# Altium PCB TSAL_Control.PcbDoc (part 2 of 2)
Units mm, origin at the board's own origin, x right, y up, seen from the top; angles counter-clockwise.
Board outline 110 x 55.6 mm, 4 copper layers (Top Layer, GND, PWR, Bottom Layer), stack 1.488 mm thick; 121 components, 67 nets, 352 pads, 66 vias.
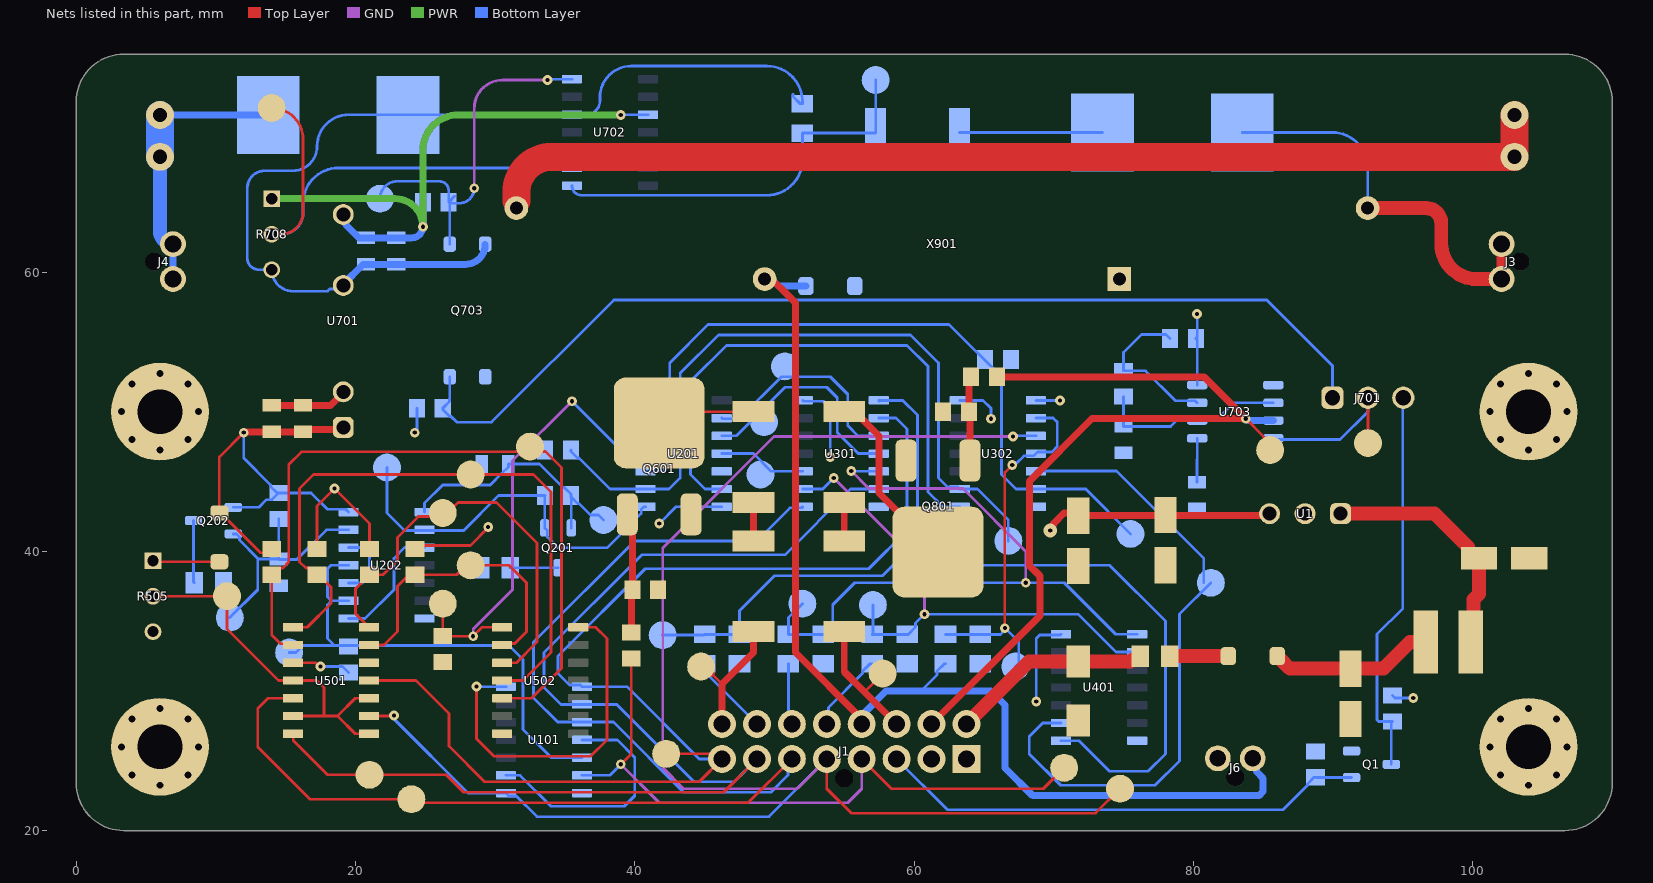
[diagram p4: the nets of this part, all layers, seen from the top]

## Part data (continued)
U301: library part CMP-00216-1, "XOR Gate, 4000/14000/40000 Series, 4-Func, 2-Input, CMOS, PDSO14", Case/Package=SOP, Load Capacitance (CL)=50pF, Max Operating Temperature=125°C, Max Supply Voltage=18V, Min Operating Temperature=-55°C, Min Supply Voltage=3V, Nominal Supply Voltage=5V, Package Body Material=Plastic, Package Equivalence Code=SOP14,.25, Package Shape=Rectangular, Package Style="SMALL OUTLINEMeter", Peak Reflow Temperature (Cel)=260°C, Power Supplies=5/15V, Temperature Grade=MILITARY
U401: library part CMP-00215-1, "NAND Gate, 4000/14000/40000 Series, 3-Func, 3-Input, CMOS, CDIP14", Case/Package=DIP, Max Operating Temperature=125°C, Max Supply Voltage=15V, Min Operating Temperature=-55°C, Min Supply Voltage=5V, Nominal Supply Voltage=10V, Package Body Material=Metal, Package Shape=Rectangular, Package Style=IN-LINEMeter, Temperature Grade=MILITARY
U501 U702: library part CMP-014-00006-1, "Comparator, 4 Func, 5000uV Offset-Max, 300ns Response Time, BIPolar, PDSO14", Case/Package=SOP, Max Operating Temperature=70°C, Min Operating Temperature=0°C, Nominal Supply Voltage=5V
U701: library part CMP-019-00001-1, "WPME-FISM Fixed Isolated SIP/SMT Module"
U703: library part CMP-00181-3, "Precision timer for -55 to 85C operation 8-SOIC -40 to 85", Case/Package=SOIC, Frequency=500kHz, High Level Output Current=-200mA, Low Level Output Current=200mA, Manufacturer="Texas Instruments", Manufacturer Part Number=SA555D, Max Operating Temperature=85°C, Max Supply Voltage=16V, Min Operating Temperature=-40°C, Min Supply Voltage=4.5V, Nominal Supply Current=2mA, Operating Supply Current=10mA, Package Quantity=75, Quiescent Current=15mA
X901: library part CMP-00224-2, "Dry Reed Relay, SPST-NC, 3500V switching voltage, 3A, 10kV isolation coil-contacts, 5504-24-1"

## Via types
v1: diameter 0.7, hole 0.5, Top Layer to Bottom Layer, tented both sides, 32 vias
v2: diameter 0.7, hole 0.3, Top Layer to Bottom Layer, tented both sides, 29 vias
v3: diameter 1.5, hole 1.5, Top Layer to Bottom Layer, tented both sides, 4 vias
v4: diameter 1, hole 0.3, Top Layer to Bottom Layer, tented both sides, 1 vias

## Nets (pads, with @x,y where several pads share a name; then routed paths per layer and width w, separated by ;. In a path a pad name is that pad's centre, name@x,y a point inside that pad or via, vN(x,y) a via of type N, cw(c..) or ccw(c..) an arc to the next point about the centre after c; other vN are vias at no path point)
+5TS: C701.1 C702.1 R706.1 R708.1 U701.4 U702.3 | length 43.9
  PWR w0.5: R708.1@14,65.25 22.825,65.25 cw(c22.825,63.25) v2(24.825,63.25) 24.825,68.71 cw(c27.365,68.71) 27.365,71.25 v2(39,71.25)
  Bottom Layer w0.2: v2(39,71.25) 39.02,71.27 U702.3@40.95,71.27
  Bottom Layer w0.5: U701.4@19.125,64.12 19.316,63.929 19.316,63.384 20.25,62.45 C701.1@22.921,62.45 ; C701.1@22.921,62.45 24.025,62.45 ccw(c24.025,63.25) v2(24.825,63.25) R706.1@24.825,65
+12: C3.1 C4.1 C703.1 C704.1 D501.K J1.7 Q202.G R1.1 R111.2 R202.1 R501.1 R502.1 R503.1 R504.1 R702.1 R704.1 U1.3 U101.14 U201.14 U202.14 U301.14 U302.1 U302.14 U401.14 U501.3 U502.14 U701.1 U703.8 | length 126.5
  Top Layer w0.2: v2(12,48.5) 10.25,46.75 D501.K@10.25,42.75 10.35,42.75 13.2,39.9 13.725,39.9 R502.1@14,40.175 ; U501.3@15.525,32.02 17.133,32.02 v2@17.403,31.75 ; R501.1@17.25,40.175 17.25,43.25 v2(18.5,44.5) 21,42 R503.1@21,40.175 ; R504.1@24.5,40.175 24.75,40.425 28.234,40.425 29.5,41.691 v2(29.5,41.75) ; v2(28.669,30.328) 28.669,26.581 29.919,25.331 36.831,25.331 38,26.5 38,33.75 37.19,34.56 U502.14@35.95,34.56
  Top Layer w0.5: v2(12,48.5) 12.054,48.5 12.104,48.55 C703.1@14,48.55 C704.1@16.25,48.55 16.415,48.715 18.96,48.715 U701.1@19.125,48.88 ; v4(69.75,41.5) 69.75,41.635 70,41.885 70,42 70.75,42.75 71.55,42.75 C3.1@71.75,42.55 85.31,42.55 U1.3@85.46,42.7
  Bottom Layer w0.2: Q202.G@11.25,43.15 13.069,43.15 13.619,43.7 14.025,43.7 R202.1@14.5,44.175 ; v2(12,48.5) 12,46.675 13.925,44.75 13.925,44.65 14.4,44.175 R202.1@14.5,44.175 ; v2(17.5,31.75) 19.075,31.75 R111.2@19.5,31.325 ; U202.14@19.5,42.81 19.3,43.01 17.99,43.01 16.825,44.175 R202.1@14.5,44.175 ; v2(24.25,48.5) 24.4,48.65 R702.1@24.4,50.25 ; v2(28.669,30.328) 28.672,30.328 28.75,30.25 28.81,30.31 U101.14@30.775,30.31 ; v2@41.768,42 42.958,43.19 U201.14@46.225,43.19 ; U301.14@52.025,50.81 52.085,50.75 53.5,50.75 54,50.25 v2(54,46.75) ; U302.14@63.275,50.81 64.94,50.81 65.5,50.25 v2(65.5,49.5) ; U302.1@68.725,50.81 v2(70.44,50.81) ; v2(68.75,29.25) 68.75,33.75 69,34 70.465,34 U401.14@70.525,34.06 ; v2(80.25,57) 80.275,56.975 80.275,55.35 R704.1@80.175,55.25 80.275,55.15 U703.8@80.275,51.905 ; R1.1@94.25,29.675 94.425,29.5 v2(95.75,29.5)
  other v2: 41.75,42
AIR+_Coil: AIR+_COIL.1 R3.2 R4.1 U301.1 U401.8 | length 73.9
  Bottom Layer w0.2: AIR+_COIL.1@42,34 44.95,34 R3.2@45,34.05 R4.1@47.5,34.05 47.5,35.75 50,38.25 57.75,38.25 58.5,39 ; U301.1@57.535,50.75 U301.1@57.475,50.81 59.19,50.81 60.25,49.75 60.25,40.75 58.5,39 ; U401.8@70.525,26.44 71.81,26.44 74,24.25 76.75,24.25 78,25.5 78,35 74,39 58.5,39
AIR+_Coil_30V: J1.10 R3.1 | length 5.9
  Bottom Layer w0.2: R3.1@45,31.95 45.238,31.712 45.238,31.142 J1.10@48.75,27.631
AIR+_Implausibility: AIR+_IMPL.1 U201.9 U301.3 | length 15.6
  Bottom Layer w0.2: U201.9@46.225,49.54 46.265,49.5 47.5,49.5 50.5,52.5 54,52.5 55.25,51.25 55.25,49 55.98,48.27 U301.3@57.475,48.27
AIR+_SCS: AIR+_SCS.1 R502.2 U501.2 U502.5 | length 55
  Top Layer w0.2: U501.2@15.525,33.29 15.432,33.383 14.617,33.383 14,34 R502.2@14,38.325 14.475,38.8 14.8,38.8 15.225,39.225 15.225,46.225 16.125,47.125 31.483,47.125 31.513,47.156 32.094,47.156 32.125,47.125 AIR+_SCS.1@32.5,47.5 32.844,47.156 33.594,47.156 34.75,46 34.75,31.628 32.602,29.48 U502.5@30.5,29.48
AIR+_State: AIR+_STATE.1 J1.1 U101.1 U301.2 U501.11 | length 88.3
  Top Layer w0.2: U501.11@20.975,30.75 24.338,30.75 26.7,28.388 26.7,26.05 29.25,23.5 44.619,23.5 J1.1@46.25,25.131 45.763,25.131 45.393,25.5 AIR+_STATE.1@42.25,25.5
  Bottom Layer w0.2: J1.1@46.25,25.131 44.619,25.131 39.44,30.31 U101.1@36.225,30.31 36.108,30.427 35.323,30.427 34.5,31.25 34.5,32.5 40.75,38.75 56.75,38.75 59.5,41.5 59.5,48.75 58.71,49.54 U301.2@57.475,49.54
AIR-_Coil: AIR-_COIL.1 R5.2 R6.1 U301.5 U401.1 | length 50.7
  GND w0.2: v2@55.51,45.74 56.75,44.5 63.5,44.5 68,40 v2(68,37.75)
  Bottom Layer w0.2: AIR-_COIL.1@52,36.25 51,35.25 R5.2@51,34.05 53.5,34.05 53.65,34.05 54.175,34.575 54.175,36.175 55.75,37.75 70.75,37.75 74.44,34.06 U401.1@75.975,34.06 ; v2(55.5,45.75) 55.52,45.73 U301.5@57.475,45.73
AIR-_Coil_30V: J1.11 R5.1 | length 4.4
  Bottom Layer w0.2: R5.1@51,31.95 51,27.881 J1.11@51.25,27.631
AIR-_Implausibility: AIR-_IMPL.1 U201.10 U301.4 | length 16.1
  Bottom Layer w0.2: U201.10@46.225,48.27 47.27,48.27 50.75,51.75 53.75,51.75 54.5,51 54.5,48.5 56,47 U301.4@57.475,47
AIR-_SCS: AIR-_SCS.1 R503.2 U501.14 U502.3 | length 31.3
  Top Layer w0.2: U501.14@20.975,34.56 20,35.535 20,37.325 R503.2@21,38.325 21.975,38.325 23,39.35 23,41 24.5,42.5 26.164,42.5 AIR-_SCS.1@26.414,42.75 ; AIR-_SCS.1@26.25,42.75 AIR-_SCS.1@26.414,42.75 ; U502.3@30.5,32.02 31.52,32.02 33,33.5 33,40.599 30.099,43.5 27.338,43.5 26.588,42.75 AIR-_SCS.1@26.414,42.75
AIR-_State: AIR-_STATE.1 J1.2 U101.2 U301.6 U501.7 | length 86.3
  Top Layer w0.2: U501.7@15.525,26.94 15.543,26.922 15.543,26.457 18,24 AIR-_STATE.1@21,24 26.5,24 27.75,22.75 46.369,22.75 J1.2@48.75,25.131
  Bottom Layer w0.2: J1.2@48.75,25.131 47.119,23.5 44.25,23.5 38.71,29.04 U101.2@36.225,29.04 34.71,29.04 33.5,30.25 33.5,32.75 40.5,39.75 50.75,39.75 55.46,44.46 U301.6@57.475,44.46
Discharge_Resistor: J2.1 J2.2 X901.1 | length 76.6
  Top Layer w2: X901.1@31.52,65.08 31.52,65.71 cw(c34.06,65.71) 34.06,68.25 J2.1@103,68.25 J2.2@103,71.25
GND: C1.2 C2.2 C3.2 C4.2 C201.2 C202.2 C703.2 C704.2 C705.2 C706.2 D1.2 D901.A J1.8 J6.1 MH1.1 MH2.1 MH3.1 MH4.1 Q1.S Q601.S Q703.3 Q801.S R2.2 R4.2 R6.2 R8.2 R10.2 R203.2 R204.2 R333.1 R444.1 R505.2 R555.1 R602.2 R802.2 U1.2 U101.7 U201.5 U201.7 U201.12 U202.7 U301.7 U302.7 U401.7 U501.12 U502.7 U701.2 U703.1 X901.3 | length 11.1
  Top Layer w0.2: v1(3.25,26) MH1.1@6,26
  Top Layer w0.5: C703.2@14,50.45 C704.2@16.25,50.45 18.207,50.45 19.125,51.368 U701.2@19.125,51.42 ; MH3.1@104,50 v1(104,52.75)
  other v1: 6,23.25 104,23.25 4,24 8,24 102,24 106,24 8.75,26 101.25,26 106.75,26 4,28 8,28 102,28 106,28 6,28.75 104,28.75 6,47.25 104,47.25 4,48 8,48 102,48 106,48 3.25,50 8.75,50 101.25,50 106.75,50 4,52 8,52 102,52 106,52 6,52.75
HV_Accu_SCS: HV_ACCU_SCS.1 R501.2 U501.1 U502.4 | length 47.6
  Top Layer w0.2: U501.1@15.525,34.56 16.55,34.56 18.25,36.26 18.25,37.425 17.35,38.325 R501.2@17.25,38.325 16.775,38.8 16.45,38.8 16,39.25 16,44.5 17,45.5 32.75,45.5 34,44.25 34,32.75 32,30.75 U502.4@30.5,30.75
HV_Accumulator: HV_ACCU.1 J1.4 U101.8 U302.3 U501.9 | length 121.3
  Top Layer w0.2: U501.9@20.975,28.21 22.71,28.21 v2(22.75,28.25) ; J1.4@53.75,25.131 53.75,23 55.5,21.25 73,21.25 HV_ACCU.1@74.75,23
  GND w0.2: J1.4@53.75,25.131 51.619,23 43.5,23 42,24.5 42,40.25 49.981,48.231 v2(67.081,48.231)
  Bottom Layer w0.2: v2(22.75,28.25) 22.846,28.154 22.846,27.904 28.06,22.69 U101.8@30.775,22.69 30.975,22.49 31.51,22.49 33,21 49.619,21 J1.4@53.75,25.131 ; v2(67.081,48.231) 67.231,48.231 67.27,48.27 U302.3@68.725,48.27
HV_Detection_DCBus: J701.1 Q703.4 R702.2 | length 74.5
  Bottom Layer w0.2: Q703.4@26.75,52.5 26.75,50.942 26.725,50.917 26.725,50.725 R702.2@26.25,50.25 26.25,50.15 26.725,49.675 26.825,49.675 27.25,49.25 29.75,49.25 38.5,58 85.25,58 89.96,53.29 J701.1@89.96,51
HV_Detection_Trigger: HV_DET_TRIG.1 J701.2 U703.4 | length 11.9
  Top Layer w0.2: HV_DET_TRIG.1@92.5,47.75 J701.2@92.5,51
  Bottom Layer w0.2: U703.4@85.725,48.095 85.82,48 90.5,48 92.5,50 J701.2@92.5,51
Implausibilities: C201.1 IMPLAUSIBILITIES.1 Q201.S R201.2 U202.1 | length 18.7
  Bottom Layer w0.2: U202.1@24.95,42.81 24.95,43.45 26.25,44.75 29.65,44.75 30.467,45.567 30.95,46.05 C201.1@30.95,46.25 33.175,46.25 34.85,44.575 34.95,44.575 35.425,44.1 R201.2@35.425,44 35.425,43.9 R201.2@35.45,43.875 ; Q201.S@35.45,41.675 R201.2@35.45,43.875 ; IMPLAUSIBILITIES.1@37.75,42.25 37.406,42.594 36.831,42.594 36,43.425 35.9,43.425 R201.2@35.45,43.875
Implausibilities_Undelayed: IMPL_UNDLY.1 Q201.G R201.1 U201.1 U202.2 | length 27.9
  Bottom Layer w0.2: IMPL_UNDLY.1@22.25,46 22.25,42.75 23.5,41.5 27.75,41.5 30.25,44 R201.1@33.575,44 33.55,43.975 Q201.G@33.55,41.675 33.736,41.489 33.736,41.014 34.5,40.25 38,40.25 40.457,42.707 40.457,42.99 40.657,43.19 U201.1@40.775,43.19
INV_HV_Detection: J701.3 Q1.D R1.2 | length 28.1
  Bottom Layer w0.2: Q1.D@94.175,24.75 94.175,27.75 R1.2@94.25,27.825 93.275,27.825 93.158,27.942 93.158,34.069 95,35.912 95,50.96 J701.3@95.04,51
INV_HV_Detection5V: J1.6 Q1.G R2.1 | length 35.1
  Bottom Layer w0.2: J1.6@58.75,25.131 62.381,21.5 86.425,21.5 88.175,23.25 88.175,23.35 88.65,23.825 R2.1@88.75,23.825 88.775,23.8 Q1.G@91.325,23.8
Latch_Reset: C202.1 LATCH_RST.1 Q202.S R202.2 U202.13 | length 18
  Bottom Layer w0.2: LATCH_RST.1@11,35.25 13,37.25 13,39.5 ; Q202.S@11.25,41.25 11.469,41.25 11.69,41.03 11.69,40.81 13,39.5 ; R202.2@14.5,42.325 C202.1@14.5,39.45 ; U202.13@19.5,41.54 17.923,41.54 15.79,39.407 14.543,39.407 C202.1@14.5,39.45 ; 13,39.5 13.05,39.45 C202.1@14.5,39.45
LV+_in: D1.1 F1.1 J1.16 | length 14.6
  Top Layer w1: J1.16@63.75,27.631 68.22,32.1 D1.1@71.75,32.1 75.489,32.1 75.614,32.225 76.075,32.225 76.2,32.35 F1.1@76.2,32.5
NetC1_1: C1.1 D2.K L1.1 | length 11.8
  Top Layer w1: D2.K@86,32.5 86,32.4 86.05,32.35 86.15,32.35 86.9,31.6 C1.1@91.25,31.6 93.6,31.6 95.5,33.5 L1.1@96.625,33.5
NetC2_1: C2.1 L1.2 U1.1 | length 17.8
  Top Layer w1: U1.1@90.54,42.7 97.25,42.7 99.65,40.3 99.65,39.8 99.95,39.5 C2.1@100.45,39.5 100.45,36.95 100.061,36.561 100.061,33.686 L1.2@99.875,33.5
NetC705_1: C705.1 U703.5 | length 3.2
  Bottom Layer w0.2: C705.1@80.25,44.95 80.25,46.587 80.275,46.612 U703.5@80.275,48.095
NetC706_1: C706.1 R705.2 U703.2 U703.6 | length 13.5
  Bottom Layer w0.2: R705.2@75,51.075 C706.1@75,48.95 78.374,48.95 78.789,49.365 U703.6@80.275,49.365 81.615,49.365 82.885,50.635 U703.2@85.725,50.635
NetD2_A: D2.A F1.2 | length 4.2
  Top Layer w1: F1.2@78.3,32.5 D2.A@82.5,32.5
NetD501_A: D501.A R505.1 | length 4.8
  Top Layer w0.2: R505.1@5.5,39.33 5.58,39.25 D501.A@10.25,39.25
NetQ201_D: Q201.D R203.1 | length 3.5
  Bottom Layer w0.2: R203.1@31.071,38.829 R203.1@31.141,38.829 ; R203.1@31.141,38.9 31.216,38.825 Q201.D@34.5,38.825
NetQ202_D: Q202.D R204.1 | length 4.5
  Bottom Layer w0.2: Q202.D@8.4,42.2 8.4,37.8 R204.1@8.45,37.75
NetQ601_D: Q601.D R604.2 | length 7.1
  Top Layer w0.2: Q601.D@41.75,49.2 42.55,50 R604.2@48.5,50
NetQ601_G: Q601.G R601.2 R602.1 | length 8.7
  Top Layer w0.5: Q601.G@39.464,42.65 39.825,42.289 R602.1@39.825,37.25 39.75,37.175 R601.2@39.75,34.175
NetQ801_D: Q801.D R804.2 | length 13.3
  Top Layer w0.5: R804.2@55,50 55.75,50 57.5,48.25 57.5,44.164 Q801.D@61.714,39.95
NetQ801_G: Q801.G R801.2 R802.1 | length 6.1
  Top Layer w0.5: Q801.G@64,46.5 64,49.925 R802.1@63.925,50 63.925,52.35 R801.2@64.075,52.5
NetR603_2: R603.2 R604.1 | length 2.7
  Top Layer w0.5: R603.2@48.5,40.75 R604.1@48.5,43.5
NetR704_2: R704.2 R705.1 U703.7 | length 11.5
  Bottom Layer w0.2: R704.2@78.325,55.25 78.05,55.525 76.275,55.525 75,54.25 R705.1@75,52.925 76.575,52.925 78.714,50.786 80.124,50.786 U703.7@80.275,50.635
NetR803_2: R803.2 R804.1 | length 2.7
  Top Layer w0.5: R803.2@55,40.75 R804.1@55,43.5
NetU101_4: U101.4 U101.9 | length 17.5
  Bottom Layer w0.2: U101.9@30.775,23.96 31.79,23.96 34,21.75 39.25,21.75 40,22.5 40,25.25 38.75,26.5 U101.4@36.225,26.5
No_Voltage_Relays_Closed: NO_HV_REL_CLS.1 R444.2 U201.3 U302.6 | length 53.6
  Bottom Layer w0.2: U201.3@40.775,45.73 41.98,45.73 42.5,46.25 42.5,53.5 45.25,56.25 62.5,56.25 66.25,52.5 66.25,45.5 67.29,44.46 U302.6@68.725,44.46 72.29,44.46 NO_HV_REL_CLS.1@75.5,41.25
Not_Intentional_Relay_State: NOT_INT_REL_STATE.1 U302.5 U401.9 | length 46.4
  Bottom Layer w0.2: U302.5@68.725,45.73 68.745,45.75 74.5,45.75 80.75,39.5 NOT_INT_REL_STATE.1@80.75,37.75 ; U401.9@70.525,27.71 69.21,27.71 68.25,26.75 68.25,25.5 70.5,23.25 77.25,23.25 79,25 79,35.5 NOT_INT_REL_STATE.1@81.25,37.75
Not_Safe_State: U202.10 U202.12 | length 4.9
  Bottom Layer w0.2: U202.10@19.5,37.73 20.48,37.73 21,38.25 21,39.75 20.48,40.27 U202.12@19.5,40.27
Out_HV_Comparator: Out_HV_Comparator.1 Q703.1 R706.2 U702.14 | length 27
  GND w0.2: v2@28.5,65.785 v2(28.5,66) 28.5,71.71 cw(c30.54,71.71) 30.54,73.75 v2(33.75,73.75)
  Bottom Layer w0.2: Out_HV_Comparator.1@21.75,65.25 cw(c23,65.25) 23,66.5 26,66.5 cw(c26,65.825) 26.675,65.825 R706.2@26.675,65 ; Q703.1@26.75,62 R706.2@26.75,64.925 ; R706.2@27.108,65.433 R706.2@26.675,65 ; v2(28.5,66) cw(c27.425,66) 27.425,64.925 R706.2@26.75,64.925 ; v2(33.75,73.75) 33.81,73.81 U702.14@35.5,73.81 ; R706.2@26.675,65 cw(c26.675,64.925) R706.2@26.75,64.925
Precharge_Coil: PRE_COIL.1 R7.2 R8.1 U301.9 U401.2 | length 38
  GND w0.2: v2(54.25,45.25) 60.75,38.75 v2(60.75,35.5)
  Bottom Layer w0.2: U301.9@52.025,44.46 53.46,44.46 v2(54.25,45.25) ; PRE_COIL.1@57.05,36.158 57.05,34.1 R7.2@57,34.05 59.583,34.05 60.107,34.575 60.107,34.857 v2(60.75,35.5) 71.75,35.5 74.46,32.79 U401.2@75.975,32.79
Precharge_Coil_30V: J1.12 R7.1 | length 5.8
  Bottom Layer w0.2: J1.12@53.75,27.631 53.863,27.744 53.863,28.813 56.325,31.275 56.325,31.425 56.85,31.95 R7.1@57,31.95
Precharge_Implausibility: PRE_IMPL.1 U201.11 U301.10 | length 6.3
  Bottom Layer w0.2: U201.11@46.225,47 48.5,47 49.77,45.73 U301.10@52.025,45.73
Precharge_SCS: PRE_SCS.1 R504.2 U501.13 U502.2 | length 23.3
  Top Layer w0.2: U501.13@20.975,33.29 22.04,33.29 23,34.25 23,37.5 23.642,38.142 24.317,38.142 24.5,38.325 27.252,38.325 27.502,38.575 27.825,38.575 PRE_SCS.1@28.25,39 ; PRE_SCS.1@27.584,38.821 PRE_SCS.1@27.584,38.834 ; PRE_SCS.1@27.825,38.594 PRE_SCS.1@27.584,38.834 ; PRE_SCS.1@28.575,39.325 PRE_SCS.1@28.25,39 ; U502.2@30.5,33.29 30.612,33.402 31.407,33.402 32.25,34.245 32.25,37.75 31,39 PRE_SCS.1@28.25,39 ; PRE_SCS.1@27.584,38.834 27.75,39 PRE_SCS.1@28.25,39
Precharge_State: J1.3 PRE_STATE.1 U101.3 U301.8 U501.5 | length 96.9
  Top Layer w0.2: U501.5@15.525,29.48 13.73,29.48 13,28.75 13,26 16.75,22.25 PRE_STATE.1@24,22.25 24.25,22 48.119,22 J1.3@51.25,25.131
  Bottom Layer w0.2: J1.3@51.25,25.131 50.971,24.852 50.971,23.971 49.75,22.75 43.5,22.75 38.48,27.77 U101.3@36.225,27.77 34.48,27.77 32.75,29.5 32.75,33.5 40,40.75 48.75,40.75 51.117,43.117 51.952,43.117 U301.8@52.025,43.19
Relays_Implausibility: R333.2 RELAYS_IMPL.1 U201.2 U302.9 | length 53.3
  Bottom Layer w0.2: R333.2@35.425,47.25 35.425,47.15 35.9,46.675 36,46.675 38.215,44.46 U201.2@40.775,44.46 42.46,44.46 43.25,45.25 43.25,52.75 46,55.5 59.75,55.5 61.75,53.5 61.75,45.25 62.398,44.602 63.133,44.602 U302.9@63.275,44.46 64.54,44.46 66.75,42.25 RELAYS_IMPL.1@66.75,40.75
Relays_State_Detection: RELAY_STATE_DET.1 U201.13 U302.8 | length 42.2
  Bottom Layer w0.2: U201.13@46.225,44.46 45.04,44.46 44,45.5 44,52.183 46.567,54.75 59.5,54.75 61,53.25 61,44.25 62.06,43.19 U302.8@63.275,43.19 63.25,43.165 RELAY_STATE_DET.1@63.25,40.75
Safe_State: R111.1 SAFE_STATE.1 U101.5 U202.9 U202.11 | length 36.2
  Bottom Layer w0.2: SAFE_STATE.1@15.25,32.75 15.737,32.75 16.237,33.25 18.5,33.25 ; U202.9@19.5,36.46 18.29,36.46 ; U202.11@19.5,39 18.25,39 18,38.75 18,36.75 18.29,36.46 ; U101.5@36.225,25.23 34.02,25.23 32,27.25 32,32.25 31,33.25 19.5,33.25 18.5,33.25 ; 18.29,36.46 18,36.17 18,33.75 18.5,33.25
Safe_State_Unlatched: U202.3 U202.8 | length 8.9
  Bottom Layer w0.2: U202.8@19.5,35.19 20.69,35.19 22.75,37.25 22.75,39.5 23.52,40.27 U202.3@24.95,40.27
SC_End: R9.2 R10.1 SC_END.1 U302.2 U302.4 | length 26.9
  Top Layer w0.2: v2(66.5,34.5) 66.5,45.655 v2(67.034,46.188)
  Bottom Layer w0.2: R9.2@62.25,34.05 R10.1@64.75,34.05 66.196,34.05 66.404,34.258 66.404,34.404 v2(66.5,34.5) 67.5,33.5 67.5,32 SC_END.1@67.25,31.75 ; v2(67.034,46.188) 67.129,46.284 67.313,46.284 67.867,46.838 68.563,46.838 U302.4@68.725,47 68.847,47.122 69.872,47.122 70.25,47.5 70.25,49.25 69.96,49.54 U302.2@68.725,49.54
SC_End_30V: D901.K J1.13 J6.2 R9.1 X901.2 | length 80
  Top Layer w0.5: X901.2@49.3,60 51.5,57.8 51.5,32.75 56.25,28 J1.13@56.25,27.631
  Bottom Layer w0.2: 60.5,30 61.642,31.142 61.642,31.425 62.167,31.95 R9.1@62.25,31.95
  Bottom Layer w0.5: X901.2@49.3,60 50.3,59 D901.K@52.25,59 ; J1.13@56.25,27.631 56.537,27.918 56.537,28.537 58,30 60.5,30 65.5,30 66.5,29 66.5,24.5 68.5,22.5 84.707,22.5 85,22.793 85,23.75 84.508,24.242 84.508,24.922 J6.2@84.25,25.18
SCS_Error: R555.2 SCS_ERROR.1 U201.4 U502.1 | length 33.4
  Top Layer w0.2: SCS_ERROR.1@26.25,36.25 R555.2@26.25,33.925 v2(28.425,33.925) 29.06,34.56 U502.1@30.5,34.56
  GND w0.2: v2(28.425,33.925) 28.435,33.935 28.435,34.435 31.25,37.25 31.25,46.5 v2(35.5,50.75)
  Bottom Layer w0.2: v2(35.5,50.75) 39.25,47 U201.4@40.775,47
TS+_DCBus1: F3.1 R709.1 | length 10.2
  Bottom Layer w0.2: R709.1@63.25,70 F3.1@73.5,70
TS+_DCBus1_Unfused: F3.2 J3.1 J3.2 X901.4 | length 28.4
  Top Layer w0.75: J3.1@102.07,59.5 J3.2@102.07,62
  Top Layer w1: X901.4@92.48,64.58 96.67,64.58 cw(c96.67,63.5) 97.75,63.5 97.75,62.04 ccw(c100.29,62.04) 100.29,59.5 J3.1@102.07,59.5
  Bottom Layer w0.2: F3.2@83.5,70 89.94,70 cw(c89.94,67.46) 92.48,67.46 X901.4@92.48,65.08
TS-: C701.2 C702.2 F4.1 Q703.2 R708.2 R710.2 U701.3 U702.12 | length 72.6
  Bottom Layer w0.2: U701.3@19.125,59.04 18.876,58.791 18.146,58.791 17.975,58.62 15.55,58.62 cw(c15.55,60.17) R708.2@14,60.17 13.08,60.17 cw(c13.08,61) 12.25,61 12.25,66 cw(c13.5,66) 13.5,67.25 15.5,67.25 ccw(c15.5,69) 17.25,69 cw(c19.52,69) 19.52,71.27 23.75,71.27 U702.12@35.5,71.27 36.52,71.27 ccw(c36.52,72.25) 37.5,72.25 37.5,72.5 cw(c39.75,72.5) 39.75,74.75 49.46,74.75 cw(c49.46,72.21) 52,72.21 R710.2@52,72.05 51.85,72.05 51.325,72.575 51.325,72.725
  Bottom Layer w0.5: U701.3@19.125,59.04 19.125,59.125 20.55,60.55 C701.2@22.921,60.55 ; C701.2@22.921,60.55 27.873,60.55 ccw(c27.873,61.968) Q703.2@29.29,61.968
TS-_Unfused: F4.2 J4.1 J4.2 J5.1 J5.2 | length 20
  Bottom Layer w0.5: J5.1@6,71.25 F4.2@13.75,71.25 ; J4.2@6.93,59.5 J4.1@6.93,62
  Bottom Layer w1: J5.2@6,68.25 6,62.93 ccw(c6.93,62.93) J4.1@6.93,62
  Bottom Layer w2: J5.2@6,68.25 J5.1@6,71.25
TS_Off: J1.5 R601.1 TS_OFF.1 U101.6 | length 47.9
  Top Layer w0.2: v2(39,24.75) 39.75,25.5 R601.1@39.75,32.325 ; J1.5@56.25,25.131 58.381,23 69.25,23 TS_OFF.1@70.75,24.5
  GND w0.2: v2@39.01,24.74 41.75,22 55.25,22 56.25,23 J1.5@56.25,25.131
  Bottom Layer w0.2: U101.6@36.225,23.96 38.21,23.96 v2(39,24.75)
TS_On: J1.15 R801.1 TS_ON.1 U703.3 | length 62.3
  Top Layer w0.2: v2(83.75,49.5) 85.031,48.219 85.031,48.206 85.5,47.737 TS_ON.1@85.5,47.25
  Top Layer w0.5: J1.15@61.25,27.631 69,35.381 69,38.25 68.25,39 68.25,45 72.75,49.5 v2(83.75,49.5) 80.75,52.5 R801.1@65.925,52.5
  Bottom Layer w0.5: v2(83.75,49.5) 83.804,49.5 83.939,49.365 U703.3@85.725,49.365
TSAL_Green: J1.9 R603.1 TSAL_GREEN.1 | length 10
  Top Layer w0.2: TSAL_GREEN.1@45.487,31.263 46.25,30.5
  Top Layer w0.5: TSAL_GREEN.1@44.25,31.5 44.487,31.263 TSAL_GREEN.1@45.487,31.263 ; J1.9@46.25,27.631 46.25,30.5 48.5,32.75 R603.1@48.5,34.25
TSAL_Red: J1.14 R803.1 TSAL_RED.1 | length 10
  Top Layer w0.2: 56.44,29.94 TSAL_RED.1@57.75,31.25
  Top Layer w0.5: R803.1@55,34.25 55,31.381 56.44,29.94 J1.14@58.75,27.631
V_REF: R505.3 U501.4 U501.6 U501.8 U501.10 V_REF.1 | length 27.2
  Top Layer w0.2: R505.3@5.5,36.79 5.54,36.75 5.58,36.79 V_REF.1@10.798,36.79 10.798,34.452 14.5,30.75 U501.4@15.525,30.75 17.25,30.75 17.75,30.25 17.75,28.21 ; U501.6@15.525,28.21 17.75,28.21 ; U501.8@20.975,26.94 19.98,26.94 18.71,28.21 ; U501.10@20.975,29.48 19.98,29.48 18.71,28.21 ; 17.75,28.21 18.71,28.21
Voltage_DCBus1: R709.2 R710.1 U702.8 Voltage_DCBus1.1 | length 29.3
  Bottom Layer w0.2: U702.8@35.5,66.19 ccw(c36.19,66.19) 36.19,65.5 49.46,65.5 ccw(c49.46,68.04) 52,68.04 R710.1@52,69.95 57.2,69.95 ccw(c57.2,70) R709.2@57.25,70 Voltage_DCBus1.1@57.25,73.75
VREF_HV_Detection: R708.3 TP703.1 U702.9 | length 36.4
  Top Layer w0.2: R708.3@14,62.71 14.653,62.71 ccw(c14.653,64.307) 16.25,64.307 16.25,69.5 ccw(c14,69.5) TP703.1@14,71.75
  Bottom Layer w0.2: R708.3@14,62.71 14.71,62.71 ccw(c14.71,64.25) 16.25,64.25 16.25,64.92 cw(c18.79,64.92) 18.79,67.46 U702.9@35.5,67.46
pads on no net: J1.A J3. J4. J6. U101.10 U101.11 U101.12 U101.13 U201.6 U201.8 U202.4 U202.5 U202.6 U301.11 U301.12 U301.13 U302.10 U302.11 U302.12 U302.13 U401.3 U401.4 U401.5 U401.6 U401.10 U401.11 U401.12 U401.13 U502.6 U502.8 U502.9 U502.10 U502.11 U502.12 U502.13 U702.1 U702.2 U702.4 U702.5 U702.6 U702.7 U702.10 U702.11 U702.13
copper on no net:
  other v3: 101.1,65.1 7.9,65.3 101.1,74.2 7.9,74.4

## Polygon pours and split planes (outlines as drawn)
GND on Bottom Layer "GND_L04_P006" (solid, pour order 6): 0,23.414 0,72 0,72.186 cw(c3.414,72.186) 3.414,75.6 106.5,75.6 106.586,75.6 cw(c106.586,72.186) 110,72.186 110,72 110,23.414 cw(c106.586,23.414) 106.586,20 106.5,20 3.414,20 cw(c3.414,23.414)
GND on Top Layer "GND_L01_P005" (solid, pour order 5): 0,23.414 0,72 0,72.186 cw(c3.414,72.186) 3.414,75.6 106.5,75.6 106.586,75.6 cw(c106.586,72.186) 110,72.186 110,72 110,23.414 cw(c106.586,23.414) 106.586,20 106.5,20 3.414,20 cw(c3.414,23.414)
GND on GND "GND_L02_P007" (solid, pour order 7): 3.414,20 cw(c3.414,23.414) 0,23.414 0,72 0,72.186 cw(c3.414,72.186) 3.414,75.6 106.5,75.6 106.586,75.6 cw(c106.586,72.186) 110,72.186 110,72 110,23.414 cw(c106.586,23.414) 106.586,20 106.5,20
+12 on PWR "+12_L03_P008" (solid, pour order 8): 3.414,20 cw(c3.414,23.414) 0,23.414 0,72 0,72.186 cw(c3.414,72.186) 3.414,75.6 106.5,75.6 106.586,75.6 cw(c106.586,72.186) 110,72.186 110,72 110,23.414 cw(c106.586,23.414) 106.586,20 106.5,20

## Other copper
Top Layer:
  pour cut-out: 0,75.5 0,53.5 28,53.5 35.5,61 88.75,61 96.25,53.5 110,53.5 110,75.5
GND:
  pour cut-out: 110,53.75 96,53.75 88.75,61 35.5,61 28.25,53.75 0,53.75 0,75.5 110,75.5
PWR:
  pour cut-out: 110,53.75 96,53.75 88.75,61 35.5,61 28.25,53.75 0,53.75 0,75.5 110,75.5
  pour cut-out: 18.081,49.52 18.242,49.718 18.625,49.718 19.698,49.718 20.258,49.158 20.258,47.762 19.728,47.233 18.272,47.233 17.773,47.732 17.773,49.212
  pour cut-out: 85.295,43.95 85.978,43.95 86.625,43.303 86.625,42.097 86.063,41.535 84.857,41.535 84.21,42.182 84.21,43.218 84.942,43.95
Bottom Layer:
  pour cut-out: 0,75.5 0,53.5 28,53.5 35.5,61 88.75,61 96.25,53.5 110,53.5 110,75.5

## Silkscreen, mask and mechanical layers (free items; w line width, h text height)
Top Overlay:
  drawing of 71 lines, arcs and shapes, not listed
  text "R_Dsch-" at 1.208,73.248 h2.5 r270
  text "Discharge Relay" at 98.067,72.748 h2.5 r270
  text "R_Dsch+" at 107.208,71.998 h2.5 r270
  text "TS" at 17.506,69.5 h7
  text "TS" at 91.506,66.25 h7
  text "TS-" at 0.75,61.998 h2.5 r270
  text "TS+" at 107.5,61.998 h2.5 r270
  text "4 mm" at 55,61.75 h1.7 r90
  text "4 mm" at 104.75,54.5 h1.7 r90
  text "4 mm" at 5.5,54.25 h1.7 r90
  text "LV" at 26.006,50 h7
  text "GND" at 79.25,21 h2 r90
  text "SC END" at 87.75,21.002 h2 r90
Bottom Overlay:
  drawing of 31 lines, arcs and shapes, not listed
  text "TS" at 49.504,68.659 h7
  text "4 mm" at 54.75,64.5 h1.7 r90
  text "TS" at 99.744,61 h7
  text "TS" at 12.994,59 h7
  text "4 mm" at 104.75,57.5 h1.7 r90
  text "4 mm" at 5.25,57 h1.7 r90
  text "LV" at 87.744,56.75 h7
  text "TSAL CONTROL 2025" at 108.748,41.5 h2.5
  text "Guillem Ropero" at 108.75,39.775 h2.5
  text "LV" at 20.744,23 h7
Mechanical 1:
  lines w1: 0,72 0,23.414 ccw(c3.414,23.414) 3.414,20 106.5,20 ; 0,72.186 cw(c3.414,72.186) 3.414,75.6 106.5,75.6 ; 106.586,20 ccw(c106.586,23.414) 110,23.414 110,72 ; 106.586,75.6 cw(c106.586,72.186) 110,72.186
